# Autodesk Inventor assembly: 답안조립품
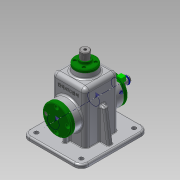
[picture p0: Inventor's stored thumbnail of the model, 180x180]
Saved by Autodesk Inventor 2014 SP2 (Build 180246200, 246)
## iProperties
Created: 2016-08
Part Number: 답안조립품
Document SubType Name: Assembly
Designer: user
Author: user
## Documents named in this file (18)
- C:\Users\user\Desktop\460820V1013\답안조립품.iam
- C:\Users\user\Desktop\460820V1013\본체.ipt
- C:\Users\user\Desktop\460820V1013\뒤커버.ipt
- C:\Users\user\Desktop\460820V1013\앞커버.ipt
- C:\Users\user\Desktop\460820V1013\베어링 15 x 35 x 11.ipt
- C:\Users\user\Desktop\460820V1013\편심축.ipt
- C:\Users\user\Desktop\460820V1013\V-벨트풀리.ipt
- C:\Users\user\Desktop\460820V1013\키 5 x 5 x 14.ipt
- C:\Users\user\Desktop\460820V1013\볼트 M6 x 12.ipt
- C:\Users\user\Desktop\460820V1013\와셔.ipt
- C:\Users\user\Desktop\460820V1013\멈춤링 6 x 5.ipt
- C:\Users\user\Desktop\460820V1013\멈춤링 15 x 1.ipt
- C:\Users\user\Desktop\460820V1013\오일실 15 25 7.ipt
- C:\Users\user\Desktop\460820V1013\링크.ipt
- C:\Users\user\Desktop\460820V1013\슬라이드바.ipt
- C:\Users\user\Desktop\460820V1013\고정핀.ipt
- C:\Users\user\Desktop\460820V1013\상부부시.ipt
- C:\Users\user\Desktop\460820V1013\볼트 M4 x 10.ipt
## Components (5 placed, 4 different names)
1. V-벨트풀리:1 — 각도:1
2. ISO 4018 M6 x 12:1 — 강체:1
3. 고정핀:1
4. ISO 4762 M4 x 10:1 — 강체:4
5. ISO 4762 M4 x 10:2 — 강체:5
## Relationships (4: WeldJoint 3, Angle 1)
- 각도:1 [Angle]: V-벨트풀리:1
- 강체:1 [WeldJoint]: ISO 4018 M6 x 12:1
- 강체:4 [WeldJoint]: ISO 4762 M4 x 10:1
- 강체:5 [WeldJoint]: ISO 4762 M4 x 10:2
